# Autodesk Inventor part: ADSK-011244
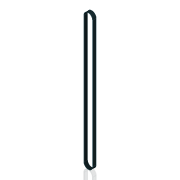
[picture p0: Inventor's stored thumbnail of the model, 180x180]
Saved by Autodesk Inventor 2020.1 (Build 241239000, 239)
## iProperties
Created: 1999-12
Part Number: ADSK-011244
Document SubType Name: Modeling
Designer: sspink
Material: Générique
Density: 1 g/cm^3
Appearance: Servo Black
Mass: 361.613 g
Surface Area: 2467.7 cm^2
Volume: 361.613 cm^3
Control State: 0
Master: False
Checked Out: False
Shininess: 0.0
Length Units: 11269
Angle Units: 11279
Time Units: 11290
Mass Units: 11283
Length Display Precision: 3
Angle Display Precision: 2
Compacted: True
Dimensions: 95,3x1445,3x38,1 mm
Mass: 0,362 kg
DocNumber: ADSK-011244.ipt
Folder: 01 - Themengebiete\Simplification\01 - Packaging machine\
VDS_Category: 3D Komponenten
Density: 0.0
Volumn: 0.0
Area: 0.0
PropertySet Name: Model Information
Author: sspink
Revision Number: -
Title: belt
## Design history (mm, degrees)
node "Solide1"
  node "Extrusion1" dims "d5" = 38.1, "d6" = 0
sketch "Sketch1"
  geometry: L1 (-47.638, 0)-(-47.638, -1350); L2 (-44.463, 0)-(-44.463, -1350); L3 (44.463, 0)-(44.463, -1350); L4 (47.638, 0)-(47.638, -1350); A1 r 44.463 centre (0, 0) between (44.463, 0) and (-44.463, 0); A2 r 47.638 centre (0, 0) between (47.638, 0) and (-47.638, 0); A3 r 44.463 centre (0, -1350) between (-44.463, -1350) and (44.463, -1350); A4 r 47.638 centre (0, -1350) between (-47.638, -1350) and (47.638, -1350); 1 further point
  constraints: 8 end point, 8 point on circle, 8 tangent, 4 centre point, 3 coincident, 1 vertical alignment
  dimensions: "d0" = 88.9254 diameter of A1; "d1" = 95.2754 diameter of A2 (computed from d0); "d2" = 88.9254 diameter of A3 (= d0); "d3" = 95.2754 diameter of A4 (= d1); "d4" = 1350 distance of A3.centre A1.centre
node "Corps solides"
node "Corps surfaciques"
